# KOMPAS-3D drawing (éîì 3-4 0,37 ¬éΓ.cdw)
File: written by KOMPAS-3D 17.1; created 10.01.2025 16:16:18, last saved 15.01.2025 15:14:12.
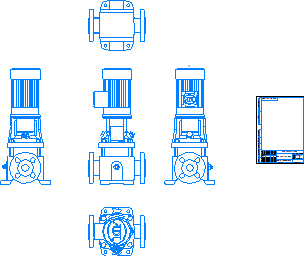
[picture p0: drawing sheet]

Sheet 1: A4, portrait

Title block, sheet 1: name: ВМН 3-4 0,37 кВт; designation: ВМН 3-4 0,37 кВт; material: Сталь 10  ГОСТ 1050-2013; mass: 64,65; sheets: 1; sheet format: A4; stored path: \\adlc.lan\data\АДЛ_ПКД\3D-модели\ADL production\Насосы ГРАНПАМП\Насосы ВМН\ВМН3\KOMPAS 3D\3-4 0,37 кВт _ ВМН.cdw

Views: Проекционный вид 2, Проекционный вид 3, Проекционный вид 4, Проекционный вид 5
Referenced files in \\adlc.lan\data\АДЛ_ПКД\3D-модели\ADL production\Насосы ГРАНПАМП\Насосы ВМН\ВМН3\KOMPAS 3D\: ВМН 3-4 0,37 кВт.m3d
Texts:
  Andrey
  АДЛ
Dimensions and other numbers on the sheet: 1:1; 1; 64,65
